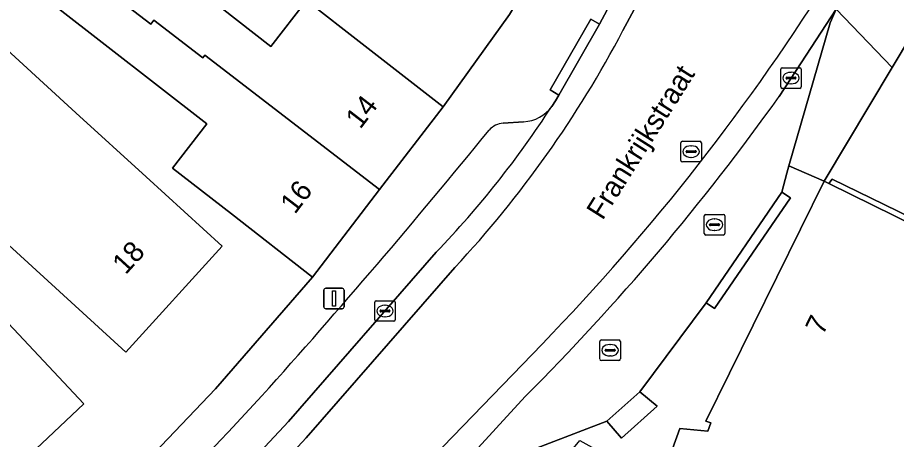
# Model space of a CAD drawing. Extents: x 160023 to 161302, y 384750 to 385707.
# Drawn here: x 160609.43 to 160652.2, y 385273.68 to 385294.19 of the extents above; entities that cross this region are included whole.
import ezdxf

# ---------------------------------------------------------------- set-up
doc = ezdxf.new("R2010")
doc.units = 0
for name, color, linetype in [('IMGEO_Erf', 7, 'Continuous'), ('IMGEO_Kolk', 7, 'Continuous'), ('IMGEO_Lichtmast', 7, 'Continuous'), ('IMGEO_Muur', 7, 'Continuous'), ('IMGEO_Openbare_ruimte_label', 7, 'Continuous'), ('IMGEO_Pand', 7, 'Continuous'), ('IMGEO_Pand_nummerreeks', 7, 'Continuous'), ('IMGEO_Parkeervlak_open', 7, 'Continuous'), ('IMGEO_Rijbaan_lokaal_open', 7, 'Continuous'), ('IMGEO_Rioolput', 7, 'Continuous'), ('IMGEO_Voetpad_open', 7, 'Continuous')]:
    doc.layers.add(name, color=color, linetype=linetype)

msp = doc.modelspace()

# ---------------------------------------------------------------- linework, layer by layer
at = {"layer": 'IMGEO_Erf'}
for points in [[(160598.991, 385257.53), (160615.424, 385272.327), (160619.066, 385276.134), (160623.779, 385281.571), (160619.834, 385284.643), (160616.963, 385286.877), (160618.633, 385289.02), (160611.294, 385294.736), (160612.6, 385296.413), (160614.303, 385298.6), (160621.759, 385292.793), (160623.496, 385295.023), (160626.197, 385292.921), (160630.142, 385289.849), (160633.365, 385294.346), (160642.053, 385308.743), (160650.395, 385323.36)], [(160653.825, 385294.836), (160651.991, 385291.772), (160648.678, 385286.238), (160648.914, 385286.122), (160649.069, 385286.341), (160654.173, 385283.853)], [(160609.221, 385279.057), (160612.65, 385275.418), (160604.496, 385267.733)]]:
    msp.add_lwpolyline(points, dxfattribs=at)
msp.add_lwpolyline([(160606.887, 385285.04), (160605.252, 385283.246), (160601.551, 385286.62), (160599.606, 385288.392), (160603.076, 385292.198), (160605.049, 385290.4), (160607.907, 385293.534), (160612.261, 385289.565), (160615.682, 385286.447), (160619.386, 385283.071), (160614.695, 385277.924)], close=True, dxfattribs=at)
at = {"layer": 'IMGEO_Kolk'}
for p, q in [((160646.569, 385290.826), (160646.569, 385291.678)), ((160646.644, 385291.752), (160647.496, 385291.752)), ((160647.57, 385291.678), (160647.57, 385290.826)), ((160646.828, 385291.246), (160646.828, 385291.258)), ((160646.871, 385291.295), (160647.269, 385291.295)), ((160647.057, 385291.532), (160647.082, 385291.532)), ((160647.312, 385291.258), (160647.312, 385291.246)), ((160647.266, 385291.209), (160646.868, 385291.209)), ((160647.08, 385290.972), (160647.055, 385290.972)), ((160647.496, 385290.752), (160646.644, 385290.752)), ((160642.848, 385283.695), (160642.848, 385284.547)), ((160642.923, 385284.621), (160643.775, 385284.621)), ((160643.849, 385284.547), (160643.849, 385283.695)), ((160643.107, 385284.115), (160643.107, 385284.127)), ((160643.545, 385284.078), (160643.147, 385284.078)), ((160643.15, 385284.164), (160643.548, 385284.164)), ((160643.336, 385284.401), (160643.361, 385284.401)), ((160643.591, 385284.127), (160643.591, 385284.115)), ((160643.775, 385283.621), (160642.923, 385283.621)), ((160643.359, 385283.841), (160643.334, 385283.841)), ((160626.808, 385279.499), (160626.808, 385280.351)), ((160626.883, 385280.425), (160627.735, 385280.425)), ((160627.296, 385280.205), (160627.321, 385280.205)), ((160627.809, 385280.351), (160627.809, 385279.499)), ((160627.067, 385279.919), (160627.067, 385279.931)), ((160627.505, 385279.882), (160627.107, 385279.882)), ((160627.11, 385279.968), (160627.508, 385279.968)), ((160627.551, 385279.931), (160627.551, 385279.919)), ((160627.735, 385279.425), (160626.883, 385279.425)), ((160627.319, 385279.645), (160627.294, 385279.645)), ((160637.767, 385277.592), (160637.767, 385278.444)), ((160637.842, 385278.518), (160638.694, 385278.518)), ((160638.768, 385278.444), (160638.768, 385277.592)), ((160638.026, 385278.012), (160638.026, 385278.024)), ((160638.069, 385278.061), (160638.467, 385278.061)), ((160638.255, 385278.298), (160638.28, 385278.298)), ((160638.51, 385278.024), (160638.51, 385278.012)), ((160638.464, 385277.975), (160638.066, 385277.975)), ((160638.278, 385277.738), (160638.253, 385277.738)), ((160638.694, 385277.518), (160637.842, 385277.518))]:
    msp.add_line(p, q, dxfattribs=at)
for points in [[(160646.569, 385290.826), (160646.569, 385291.678)], [(160646.644, 385291.752), (160647.496, 385291.752)], [(160647.57, 385291.678), (160647.57, 385290.826)], [(160647.496, 385290.752), (160646.644, 385290.752)], [(160642.848, 385283.695), (160642.848, 385284.547)], [(160642.923, 385284.621), (160643.775, 385284.621)], [(160643.849, 385284.547), (160643.849, 385283.695)], [(160643.775, 385283.621), (160642.923, 385283.621)], [(160626.808, 385279.499), (160626.808, 385280.351)], [(160626.883, 385280.425), (160627.735, 385280.425)], [(160627.809, 385280.351), (160627.809, 385279.499)], [(160627.735, 385279.425), (160626.883, 385279.425)], [(160637.767, 385277.592), (160637.767, 385278.444)], [(160637.842, 385278.518), (160638.694, 385278.518)], [(160638.768, 385278.444), (160638.768, 385277.592)], [(160638.694, 385277.518), (160637.842, 385277.518)]]:
    msp.add_lwpolyline(points, dxfattribs=at)
for centre, radius, start, end in [((160646.646, 385291.676), 0.0765, 91.552, 178.448), ((160646.646, 385291.676), 0.0765, 91.552, 178.448), ((160647.494, 385291.676), 0.0765, 1.552, 88.448), ((160647.494, 385291.676), 0.0765, 1.552, 88.448), ((160646.868, 385291.255), 0.0403, 85.8775, 175.7526), ((160646.865, 385291.245), 0.0366, 178.938, 274.7102), ((160647.269, 385291.252), 0.043, 264.8664, 352.4533), ((160647.273, 385291.257), 0.0386, 1.7309, 96.639), ((160646.646, 385290.828), 0.0765, 181.552, 268.448), ((160646.646, 385290.828), 0.0765, 181.552, 268.448), ((160647.494, 385290.828), 0.0765, 271.552, 358.448), ((160647.494, 385290.828), 0.0765, 271.552, 358.448), ((160642.925, 385284.545), 0.0765, 91.552, 178.448), ((160642.925, 385284.545), 0.0765, 91.552, 178.448), ((160643.773, 385284.545), 0.0765, 1.552, 88.448), ((160643.773, 385284.545), 0.0765, 1.552, 88.448), ((160643.147, 385284.124), 0.0403, 85.8775, 175.7526), ((160643.144, 385284.114), 0.0366, 178.938, 274.7102), ((160643.548, 385284.121), 0.043, 264.8664, 352.4533), ((160643.552, 385284.126), 0.0386, 1.7309, 96.639), ((160642.925, 385283.697), 0.0765, 181.552, 268.448), ((160642.925, 385283.697), 0.0765, 181.552, 268.448), ((160643.773, 385283.697), 0.0765, 271.552, 358.448), ((160643.773, 385283.697), 0.0765, 271.552, 358.448), ((160626.885, 385280.349), 0.0765, 91.552, 178.448), ((160626.885, 385280.349), 0.0765, 91.552, 178.448), ((160627.733, 385280.349), 0.0765, 1.552, 88.448), ((160627.733, 385280.349), 0.0765, 1.552, 88.448), ((160627.107, 385279.928), 0.0403, 85.8775, 175.7526), ((160627.104, 385279.918), 0.0366, 178.938, 274.7102), ((160627.508, 385279.925), 0.043, 264.8664, 352.4533), ((160627.512, 385279.93), 0.0386, 1.7309, 96.639), ((160626.885, 385279.501), 0.0765, 181.552, 268.448), ((160626.885, 385279.501), 0.0765, 181.552, 268.448), ((160627.733, 385279.501), 0.0765, 271.552, 358.448), ((160627.733, 385279.501), 0.0765, 271.552, 358.448), ((160637.844, 385278.442), 0.0765, 91.552, 178.448), ((160637.844, 385278.442), 0.0765, 91.552, 178.448), ((160638.692, 385278.442), 0.0765, 1.552, 88.448), ((160638.692, 385278.442), 0.0765, 1.552, 88.448), ((160638.066, 385278.021), 0.0403, 85.8775, 175.7526), ((160638.063, 385278.011), 0.0366, 178.938, 274.7102), ((160638.467, 385278.018), 0.043, 264.8664, 352.4533), ((160638.471, 385278.023), 0.0386, 1.7309, 96.639), ((160637.844, 385277.594), 0.0765, 181.552, 268.448), ((160637.844, 385277.594), 0.0765, 181.552, 268.448), ((160638.692, 385277.594), 0.0765, 271.552, 358.448), ((160638.692, 385277.594), 0.0765, 271.552, 358.448)]:
    msp.add_arc(centre, radius, start, end, dxfattribs=at)
for centre, major_axis, ratio, start_param, end_param in [((160647.056, 385291.252), (-0.387, 0.002), 0.722429, 4.712389, 7.853982), ((160647.081, 385291.252), (-0.39, 0.002), 0.717154, 1.570796, 4.712389), ((160643.335, 385284.121), (-0.387, 0.002), 0.722429, 4.712389, 7.853982), ((160643.36, 385284.121), (-0.39, 0.002), 0.717154, 1.570796, 4.712389), ((160627.295, 385279.925), (-0.387, 0.002), 0.722429, 4.712389, 7.853982), ((160627.32, 385279.925), (-0.39, 0.002), 0.717154, 1.570796, 4.712389), ((160638.254, 385278.018), (-0.387, 0.002), 0.722429, 4.712389, 7.853982), ((160638.279, 385278.018), (-0.39, 0.002), 0.717154, 1.570796, 4.712389)]:
    msp.add_ellipse(centre, major_axis=major_axis, ratio=ratio, start_param=start_param, end_param=end_param, dxfattribs=at)
at = {"layer": 'IMGEO_Lichtmast'}
for p, q in [((160624.429, 385281.036), (160625.219, 385281.036)), ((160625.219, 385281.036), (160624.429, 385281.036)), ((160624.329, 385280.136), (160624.329, 385280.936)), ((160624.329, 385280.936), (160624.329, 385280.136)), ((160625.319, 385280.936), (160625.319, 385280.136)), ((160625.319, 385280.136), (160625.319, 385280.936)), ((160625.219, 385280.036), (160624.429, 385280.036)), ((160624.429, 385280.036), (160625.219, 385280.036))]:
    msp.add_line(p, q, dxfattribs=at)
msp.add_lwpolyline([(160624.749, 385280.911), (160624.899, 385280.911), (160624.899, 385280.161), (160624.749, 385280.161), (160624.749, 385280.911)], dxfattribs=at)
for centre, start, end in [((160624.429, 385280.936), 90, 180), ((160624.429, 385280.936), 90, 180), ((160625.219, 385280.936), 0, 90), ((160625.219, 385280.936), 360, 90), ((160624.429, 385280.136), 180, 270), ((160624.429, 385280.136), 180, 270), ((160625.219, 385280.136), 270, 0), ((160625.219, 385280.136), 270, 0)]:
    msp.add_arc(centre, 0.1, start, end, dxfattribs=at)
at = {"layer": 'IMGEO_Muur'}
msp.add_lwpolyline([(160679.084, 385278.668), (160663.312, 385286.373), (160663.915, 385287.639), (160663.734, 385287.727), (160663.133, 385286.456), (160660.815, 385287.596), (160661.179, 385288.947), (160660.971, 385289.036), (160660.638, 385287.701), (160656.984, 385289.518), (160656.836, 385289.253), (160661.328, 385287.057), (160677.927, 385278.94), (160675.733, 385274.462), (160659.144, 385282.6), (160654.654, 385284.802), (160654.173, 385283.853), (160649.069, 385286.341), (160648.914, 385286.122), (160653.165, 385284.031), (160671.559, 385274.983), (160676.178, 385272.71), (160676.343, 385273.047)], close=True, dxfattribs=at)
at = {"layer": 'IMGEO_Pand'}
for points in [[(160630.142, 385289.849), (160626.197, 385292.921), (160623.496, 385295.023), (160621.759, 385292.793), (160614.303, 385298.6), (160612.6, 385296.413), (160615.912, 385293.869), (160616.065, 385294.068), (160618.442, 385292.242), (160618.537, 385292.366), (160627.05, 385285.827)], [(160627.05, 385285.827), (160618.537, 385292.366), (160618.442, 385292.242), (160616.065, 385294.068), (160615.912, 385293.869), (160612.6, 385296.413), (160611.294, 385294.736), (160618.633, 385289.02), (160616.963, 385286.877), (160619.834, 385284.643), (160623.779, 385281.571)], [(160615.682, 385286.447), (160612.261, 385289.565), (160607.907, 385293.534), (160605.049, 385290.4), (160603.076, 385292.198), (160599.606, 385288.392), (160601.551, 385286.62), (160605.252, 385283.246), (160606.887, 385285.04), (160614.695, 385277.924), (160619.386, 385283.071)], [(160671.559, 385274.983), (160653.165, 385284.031), (160648.914, 385286.122), (160648.678, 385286.238), (160642.926, 385274.57), (160643.169, 385274.482), (160643.026, 385274.089), (160641.66, 385274.22), (160640.663, 385271.476), (160644.833, 385269.176), (160648.891, 385267.409), (160650.478, 385266.833), (160660.727, 385262.941), (160663.97, 385261.763), (160664.293, 385261.646), (160665.364, 385263.611), (160668.622, 385269.591)], [(160612.65, 385275.418), (160609.221, 385279.057), (160606.443, 385282.004), (160598.923, 385274.918), (160598.287, 385274.318), (160604.496, 385267.733)]]:
    msp.add_lwpolyline(points, close=True, dxfattribs=at)
at = {"layer": 'IMGEO_Parkeervlak_open'}
for points in [[(160634.13, 385275.769), (160630.069, 385271.336), (160631.891, 385272.18), (160638.105, 385274.572), (160639.712, 385275.996), (160642.937, 385280.327), (160646.629, 385285.711), (160646.865, 385286.633), (160646.966, 385286.981), (160648.976, 385293.933), (160649.267, 385294.611), (160647.558, 385291.997), (160646.501, 385290.364)], [(160634.057, 385289.131), (160633.066, 385289.065)], [(160620.771, 385272.569), (160622.618, 385274.557), (160629.804, 385282.781)]]:
    msp.add_lwpolyline(points, dxfattribs=at)
for centre, radius, start, end in [((160553.247, 385356.867), 114.538, 314.92379, 324.50572), ((160595.327, 385315.88), 47.793, 316.1678, 327.0327), ((160633.975, 385290.914), 1.785, 272.6311, 324.3195), ((160363.307, 385507.879), 347.03, 318.0287, 320.83811), ((160633.175, 385287.989), 1.081, 95.8057, 137.1903), ((160491.147, 385395.176), 176.621, 311.29767, 317.47653)]:
    msp.add_arc(centre, radius, start, end, dxfattribs=at)
at = {"layer": 'IMGEO_Rijbaan_lokaal_open'}
for points in [[(160638.893, 385293.568), (160654.755, 385322.926), (160653.733, 385323.201), (160653.429, 385323.277), (160653.347, 385323.02), (160637.754, 385293.876), (160635.777, 385290.425), (160635.602, 385290.148), (160635.425, 385289.873)], [(160656.492, 385318.474), (160658.173, 385321.735), (160658.302, 385321.986), (160654.755, 385322.926), (160638.893, 385293.568)], [(160646.501, 385290.364), (160647.558, 385291.997), (160649.267, 385294.611), (160658.126, 385308.018), (160661.219, 385313.176), (160664.42, 385318.987), (160663.419, 385319.542), (160660.527, 385314.498)], [(160629.804, 385282.781), (160622.618, 385274.557), (160620.771, 385272.569), (160621.602, 385271.751), (160623.469, 385273.751), (160630.714, 385282.045)], [(160630.714, 385282.045), (160623.469, 385273.751), (160621.602, 385271.751), (160625.309, 385268.342), (160634.953, 385278.321)], [(160634.953, 385278.321), (160625.309, 385268.342), (160626.189, 385267.501), (160629.413, 385270.874), (160629.714, 385271.135), (160630.069, 385271.336), (160634.13, 385275.769)]]:
    msp.add_lwpolyline(points, dxfattribs=at)
for centre, radius, start, end in [((160557.323, 385353.731), 108.227, 315.83119, 328.07847), ((160557.323, 385353.731), 108.227, 315.83119, 328.07847), ((160591.86, 385318.287), 53.133, 316.9914, 332.2745), ((160591.86, 385318.287), 53.133, 316.9914, 332.2745), ((160553.247, 385356.867), 114.538, 314.92379, 324.50572), ((160595.327, 385315.88), 47.793, 316.1678, 327.0327)]:
    msp.add_arc(centre, radius, start, end, dxfattribs=at)
at = {"layer": 'IMGEO_Rioolput'}
for p, q in [((160641.708, 385287.251), (160641.708, 385288.103)), ((160641.783, 385288.177), (160642.635, 385288.177)), ((160642.196, 385287.957), (160642.221, 385287.957)), ((160642.709, 385288.103), (160642.709, 385287.251)), ((160641.967, 385287.671), (160641.967, 385287.683)), ((160642.405, 385287.634), (160642.007, 385287.634)), ((160642.01, 385287.72), (160642.408, 385287.72)), ((160642.219, 385287.397), (160642.194, 385287.397)), ((160642.451, 385287.683), (160642.451, 385287.671)), ((160642.635, 385287.177), (160641.783, 385287.177))]:
    msp.add_line(p, q, dxfattribs=at)
for points in [[(160641.708, 385287.251), (160641.708, 385288.103)], [(160641.783, 385288.177), (160642.635, 385288.177)], [(160642.709, 385288.103), (160642.709, 385287.251)], [(160642.635, 385287.177), (160641.783, 385287.177)]]:
    msp.add_lwpolyline(points, dxfattribs=at)
for centre, radius, start, end in [((160641.785, 385288.101), 0.0765, 91.552, 178.448), ((160641.785, 385288.101), 0.0765, 91.552, 178.448), ((160642.633, 385288.101), 0.0765, 1.552, 88.448), ((160642.633, 385288.101), 0.0765, 1.552, 88.448), ((160642.007, 385287.68), 0.0403, 85.8775, 175.7526), ((160642.004, 385287.67), 0.0366, 178.938, 274.7102), ((160642.408, 385287.677), 0.043, 264.8664, 352.4533), ((160642.412, 385287.682), 0.0386, 1.7309, 96.639), ((160641.785, 385287.253), 0.0765, 181.552, 268.448), ((160641.785, 385287.253), 0.0765, 181.552, 268.448), ((160642.633, 385287.253), 0.0765, 271.552, 358.448), ((160642.633, 385287.253), 0.0765, 271.552, 358.448)]:
    msp.add_arc(centre, radius, start, end, dxfattribs=at)
for centre, major_axis, ratio, start_param, end_param in [((160642.195, 385287.677), (-0.387, 0.002), 0.722429, 4.712389, 7.853982), ((160642.22, 385287.677), (-0.39, 0.002), 0.717154, 1.570796, 4.712389)]:
    msp.add_ellipse(centre, major_axis=major_axis, ratio=ratio, start_param=start_param, end_param=end_param, dxfattribs=at)
at = {"layer": 'IMGEO_Voetpad_open'}
for points in [[(160635.425, 385289.873), (160635.602, 385290.148), (160635.777, 385290.425), (160635.345, 385290.673), (160637.321, 385294.124), (160637.754, 385293.876), (160653.347, 385323.02), (160653.429, 385323.277), (160653.622, 385323.824)], [(160650.395, 385323.36), (160642.053, 385308.743), (160633.365, 385294.346), (160630.142, 385289.849), (160627.05, 385285.827), (160623.779, 385281.571), (160619.066, 385276.134), (160615.424, 385272.327), (160598.991, 385257.53), (160596.493, 385260.19), (160596.096, 385260.612), (160584.894, 385250), (160580.696, 385246.023), (160582.299, 385244.921), (160565.754, 385233.349), (160560.534, 385230.323)], [(160667.487, 385318.357), (160664.42, 385318.987), (160661.219, 385313.176), (160658.126, 385308.018), (160649.267, 385294.611), (160651.991, 385291.772), (160653.825, 385294.836)], [(160633.066, 385289.065), (160634.057, 385289.131)], [(160633.619, 385269.792), (160636.792, 385273.626), (160640.663, 385271.476), (160641.66, 385274.22), (160643.026, 385274.089), (160643.169, 385274.482), (160642.926, 385274.57), (160648.678, 385286.238), (160646.966, 385286.981), (160646.865, 385286.633), (160646.629, 385285.711), (160647.041, 385285.429), (160643.349, 385280.045), (160642.937, 385280.327), (160639.712, 385275.996), (160640.556, 385275.295), (160638.816, 385273.738), (160638.105, 385274.572), (160631.891, 385272.18), (160630.069, 385271.336), (160629.714, 385271.135), (160629.413, 385270.874), (160626.189, 385267.501), (160623.963, 385265.172)]]:
    msp.add_lwpolyline(points, dxfattribs=at)
for points in [[(160648.678, 385286.238), (160651.991, 385291.772), (160649.267, 385294.611), (160648.976, 385293.933), (160646.966, 385286.981)], [(160637.754, 385293.876), (160637.321, 385294.124), (160635.345, 385290.673), (160635.777, 385290.425)], [(160646.629, 385285.711), (160642.937, 385280.327), (160643.349, 385280.045), (160647.041, 385285.429)], [(160638.105, 385274.572), (160638.816, 385273.738), (160640.556, 385275.295), (160639.712, 385275.996)]]:
    msp.add_lwpolyline(points, close=True, dxfattribs=at)
for centre, radius, start, end in [((160633.975, 385290.914), 1.785, 272.6311, 324.3195), ((160363.307, 385507.879), 347.03, 318.0287, 320.83811), ((160633.175, 385287.989), 1.081, 95.8057, 137.1903), ((160491.147, 385395.176), 176.621, 311.29767, 317.47653)]:
    msp.add_arc(centre, radius, start, end, dxfattribs=at)

# ---------------------------------------------------------------- texts
at = {"layer": 'IMGEO_Openbare_ruimte_label'}
msp.add_text('Frankrijkstraat', height=1, rotation=57.7091, dxfattribs=at).set_placement((160637.9, 385284.3))
at = {"layer": 'IMGEO_Pand_nummerreeks'}
for s, rotation, p in [('14', 52.4518, (160626.105, 385288.733)), ('16', 52.4518, (160622.924, 385284.594)), ('18', 47.6538, (160614.684, 385281.654)), ('7', 63.7587, (160648.622, 385278.707))]:
    msp.add_text(s, height=1, rotation=rotation, dxfattribs=at).set_placement(p)

doc.saveas('drawing.dxf')
